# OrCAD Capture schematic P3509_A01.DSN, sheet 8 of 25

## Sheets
8 0017_DISPLAY PORT: size Custom
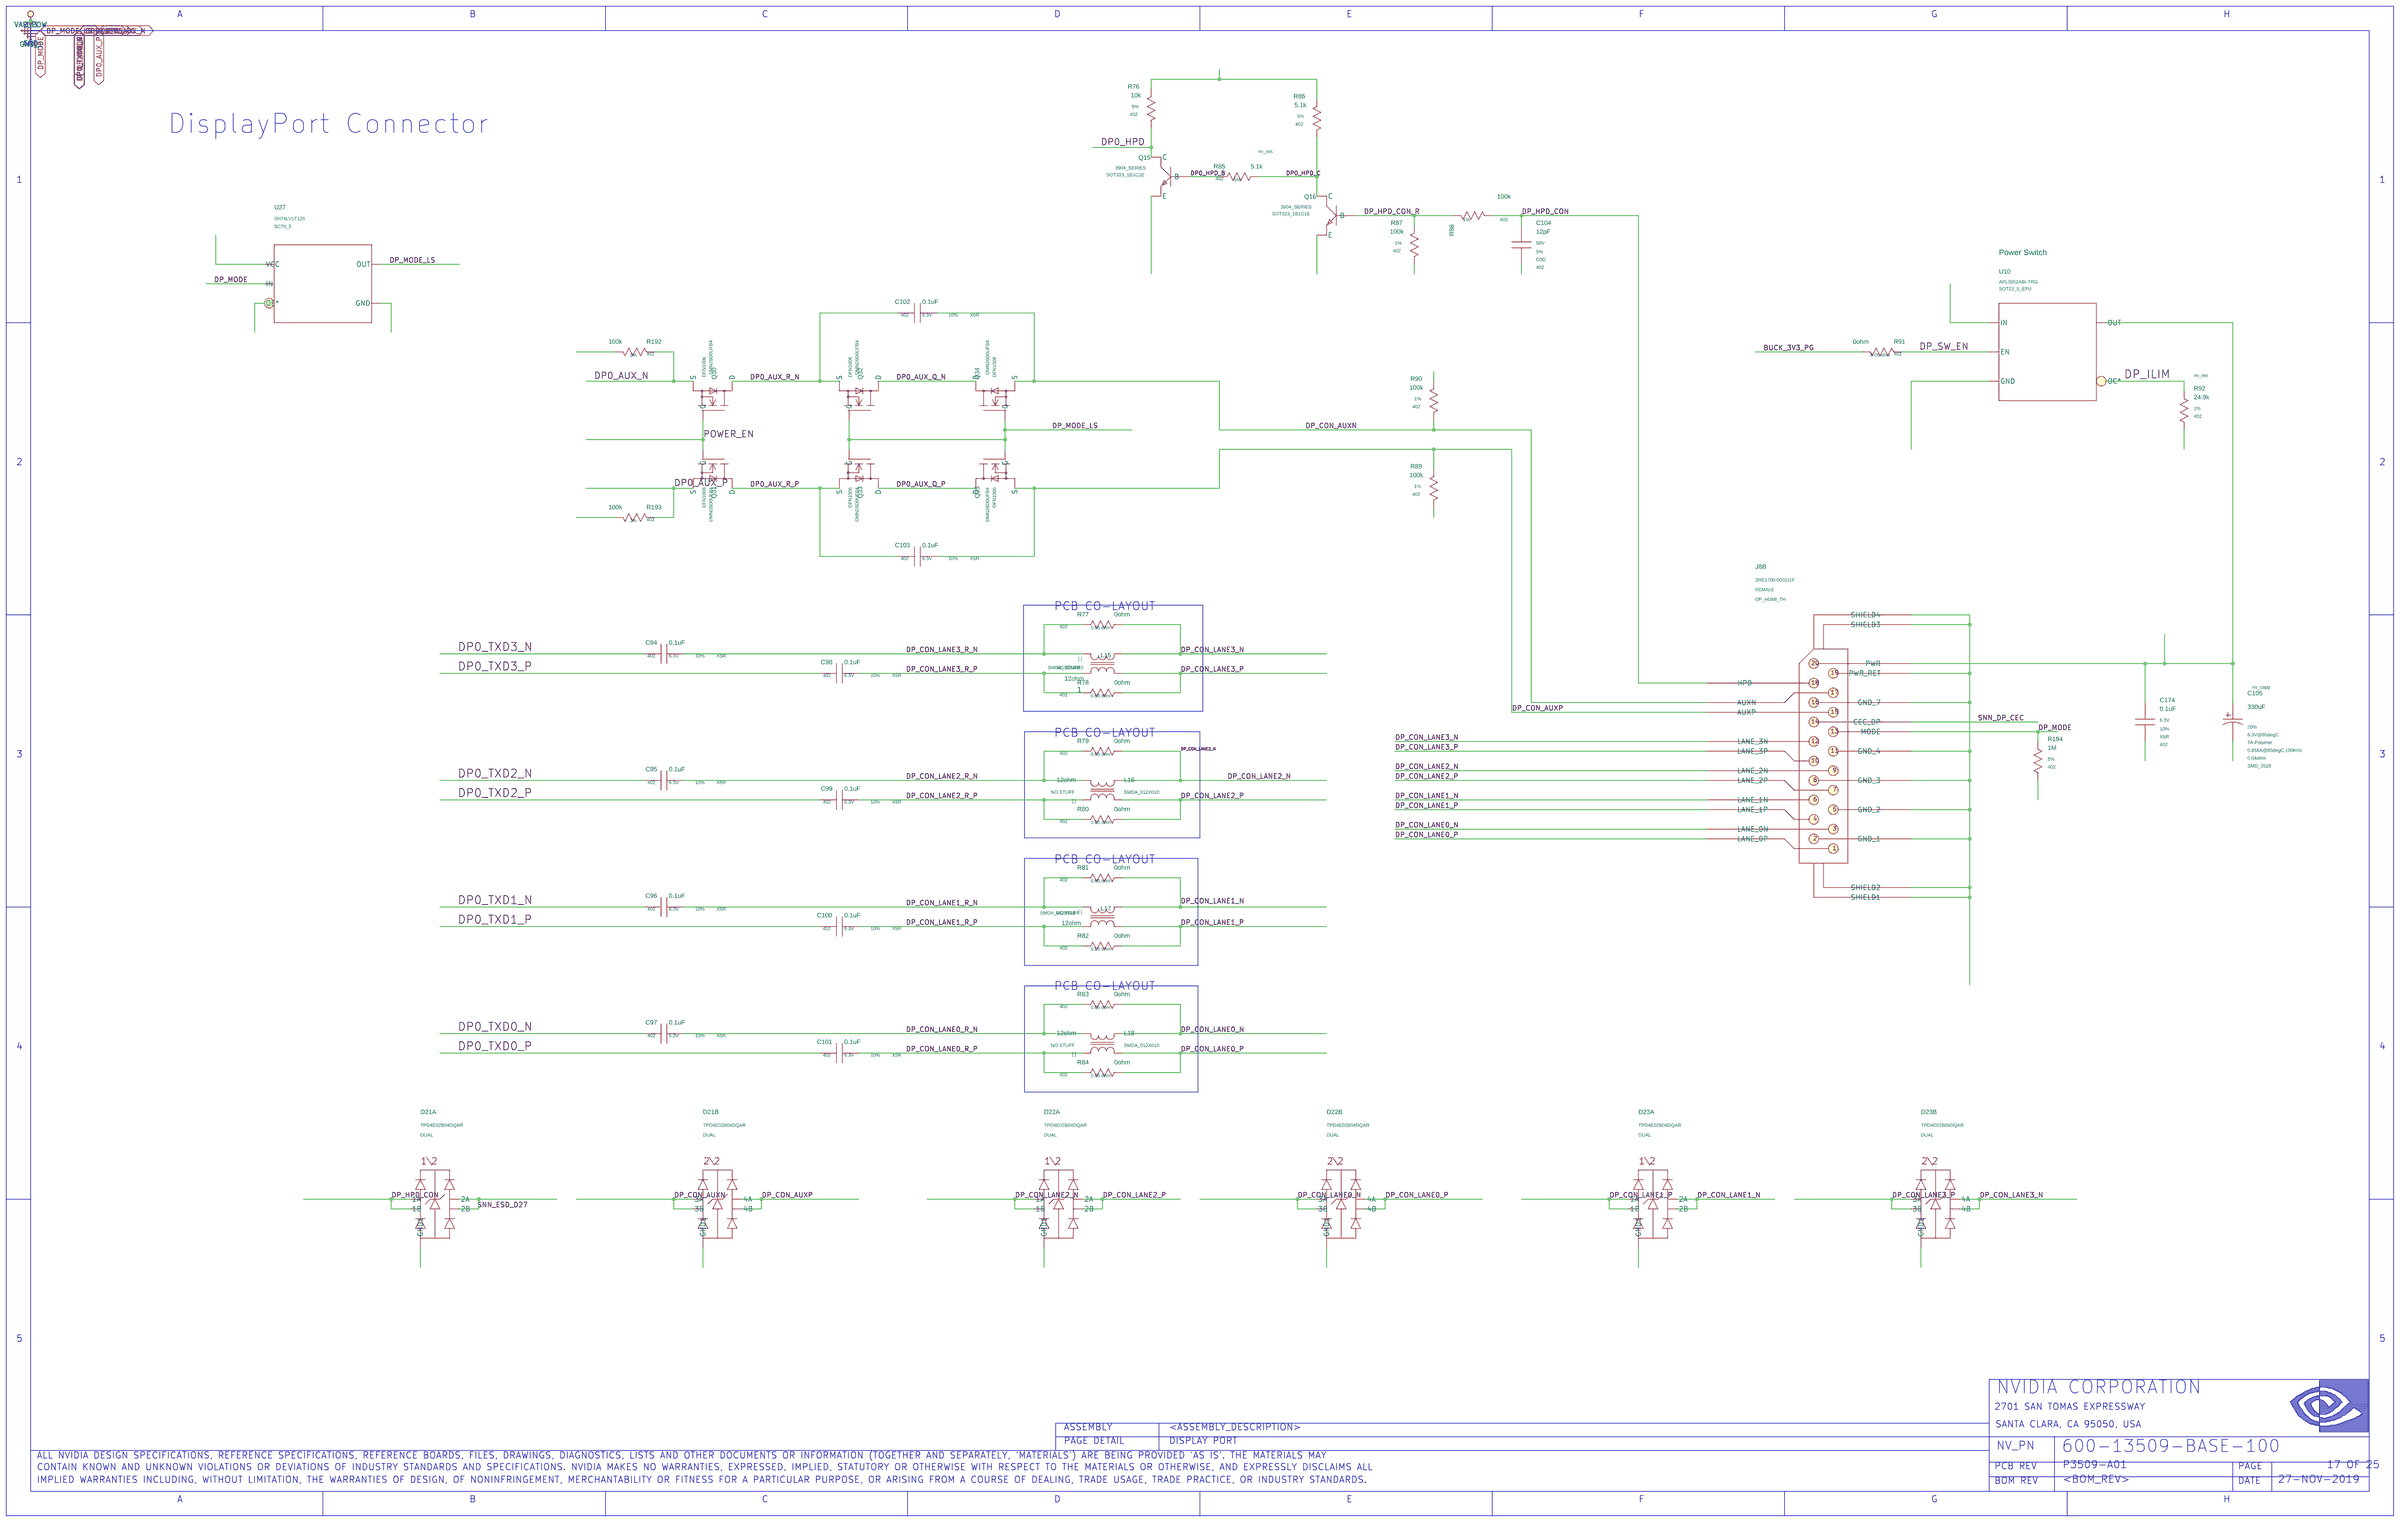
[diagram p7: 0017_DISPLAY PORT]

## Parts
sheet 0016_HDMI
J8  CON_HDMI_DISPLAYPORT  [CON_HDMI_019_DP_020_TH_RA_F_181X180_B]  (sections A,B)
sheet 0017_DISPLAY PORT
C94  0.1uF  [402]
C95  0.1uF  [402]
C96  0.1uF  [402]
C97  0.1uF  [402]
C98  0.1uF  [402]
C99  0.1uF  [402]
C100  0.1uF  [402]
C101  0.1uF  [402]
C102  0.1uF  [402]
C103  0.1uF  [402]
C104  12pF  [402]
C105  330uF  [CAP_SMD_3528]
C174  0.1uF  [402]
D21  D_ESD_DIFFPAIR  [TSLP10_P050_025X010]  (sections A,B)
D22  D_ESD_DIFFPAIR  [TSLP10_P050_025X010]  (sections A,B)
D23  D_ESD_DIFFPAIR  [TSLP10_P050_025X010]  (sections A,B)
L15  12ohm  [IND_NONRKO_SMD_012X010]
L16  12ohm  [IND_NONRKO_SMD_012X010]
L17  12ohm  [IND_NONRKO_SMD_012X010]
L18  12ohm  [IND_NONRKO_SMD_012X010]
Q15  Q_NPN  [SOT323_D]
Q16  Q_NPN  [SOT323_D]
Q30  Q_FET_N_ENH  [DFET_003_SMD_010X006_B]
Q31  Q_FET_N_ENH  [DFET_003_SMD_010X006_B]
Q32  Q_FET_N_ENH  [DFET_003_SMD_010X006_B]
Q33  Q_FET_N_ENH  [DFET_003_SMD_010X006_B]
Q34  Q_FET_N_ENH  [DFET_003_SMD_010X006_B]
Q35  Q_FET_N_ENH  [DFET_003_SMD_010X006_B]
R76  10k  [402]
R77  0ohm  [402]
R78  0ohm  [402]
R79  0ohm  [402]
R80  0ohm  [402]
R81  0ohm  [402]
R82  0ohm  [402]
R83  0ohm  [402]
R84  0ohm  [402]
R85  5.1k  [402]
R86  5.1k  [402]
R87  100k  [402]
R88  100k  [402]
R89  100k  [402]
R90  100k  [402]
R91  0ohm  [402]
R92  24.9k  [402]
R192  100k  [402]
R193  100k  [402]
R194  1M  [402]
U10  U_PWR_SW_UL  [SOT23_5]
U27  U_LEVSHFT_3STATE  [SC70_5]

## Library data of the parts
J8 = CON_HDMI_DISPLAYPORT: ANGLE: 90; ASSEMBLY: HDMI; CDS_LIB: electro_mechanic; CDS_PART_NAME: CON_HDMI_DISPLAYPORT_DP_HDMI_TH-2HE1700-000111F,FEMALE,1.4MM,90,YES,YES,YES,YES,YES,40 MV,500 MA,064-0374-000; CDS_PHYS_PART_NAME: CON_HDMI_DISPLAYPORT_DP_HDMI_TH-2HE1700-000111F,FEMALE,1.4MM,90,YES,YES,YES,YES,YES,40 MV,500 MA,064-0374-000-064-0374-000; CDS_SEC: 1; CaptureCellPackProp: CON_HDMI_DISPLAYPORTA; DEVICE_TYPENAME: CON_HDMI_DISPLAYPORT_DP_HDMI_TH-2HE1700-000111FFEMALE14MM90YESYESYESYESYES40MV500MA064-0374-000-064-0374-000; DRAWING: #NAME?; EMI_GROUND_TAB: YES; GENDER: FEMALE; LATCHING: YES; MAX_CURRENT: 500 mA; MAX_VOLTAGE: 40 mV; NV_NAME: 2HE1700-000111F; NV_PN: 064-0374-000; PACK_TYPE: DP_HDMI_TH; PATH: I25; PHYS_PAGE: 16; PITCH: 1.4mm; REFLOW: YES; ROT: 0; SEC: 1; SHIELDED: YES; SHROUDED: YES; VER: 1; XY: (-900,2900)
C94 = C: ASSEMBLY: DISPLAYPORT; CDS_LIB: discrete; CDS_PART_NAME: C_0402-0.1UF,X5R,10%,6.3V,039-0007-000; CDS_PHYS_PART_NAME: C_0402-0.1UF,X5R,10%,6.3V,039-0007-000-0.1UF,039-0007-000; CDS_SEC: 1; DEVICE_TYPENAME: C_0402-01UFX5R1063V039-0007-000-01UF039-0007-000; DRAWING: #NAME?; MAT: X5R; MAX_VOLTAGE: 6.3V; NO_XNET: 1; NV_PN: 039-0007-000; PATH: I55; PHYS_PAGE: 17; ROT: 0; SEC: 1; SIGNAL_MODEL: nv_cap; TOL: 10%; VER: 2; XY: (-8750,4300)
C95 = C: ASSEMBLY: DISPLAYPORT; CDS_LIB: discrete; CDS_PART_NAME: C_0402-0.1UF,X5R,10%,6.3V,039-0007-000; CDS_PHYS_PART_NAME: C_0402-0.1UF,X5R,10%,6.3V,039-0007-000-0.1UF,039-0007-000; CDS_SEC: 1; DEVICE_TYPENAME: C_0402-01UFX5R1063V039-0007-000-01UF039-0007-000; DRAWING: #NAME?; MAT: X5R; MAX_VOLTAGE: 6.3V; NO_XNET: 1; NV_PN: 039-0007-000; PATH: I58; PHYS_PAGE: 17; ROT: 0; SEC: 1; SIGNAL_MODEL: nv_cap; TOL: 10%; VER: 2; XY: (-8750,3650)
C96 = C: ASSEMBLY: DISPLAYPORT; CDS_LIB: discrete; CDS_PART_NAME: C_0402-0.1UF,X5R,10%,6.3V,039-0007-000; CDS_PHYS_PART_NAME: C_0402-0.1UF,X5R,10%,6.3V,039-0007-000-0.1UF,039-0007-000; CDS_SEC: 1; DEVICE_TYPENAME: C_0402-01UFX5R1063V039-0007-000-01UF039-0007-000; DRAWING: #NAME?; MAT: X5R; MAX_VOLTAGE: 6.3V; NO_XNET: 1; NV_PN: 039-0007-000; PATH: I62; PHYS_PAGE: 17; ROT: 0; SEC: 1; SIGNAL_MODEL: nv_cap; TOL: 10%; VER: 2; XY: (-8750,3000)
C97 = C: ASSEMBLY: DISPLAYPORT; CDS_LIB: discrete; CDS_PART_NAME: C_0402-0.1UF,X5R,10%,6.3V,039-0007-000; CDS_PHYS_PART_NAME: C_0402-0.1UF,X5R,10%,6.3V,039-0007-000-0.1UF,039-0007-000; CDS_SEC: 1; DEVICE_TYPENAME: C_0402-01UFX5R1063V039-0007-000-01UF039-0007-000; DRAWING: #NAME?; MAT: X5R; MAX_VOLTAGE: 6.3V; NO_XNET: 1; NV_PN: 039-0007-000; PATH: I63; PHYS_PAGE: 17; ROT: 0; SEC: 1; SIGNAL_MODEL: nv_cap; TOL: 10%; VER: 2; XY: (-8750,2350)
C98 = C: ASSEMBLY: DISPLAYPORT; CDS_LIB: discrete; CDS_PART_NAME: C_0402-0.1UF,X5R,10%,6.3V,039-0007-000; CDS_PHYS_PART_NAME: C_0402-0.1UF,X5R,10%,6.3V,039-0007-000-0.1UF,039-0007-000; CDS_SEC: 1; DEVICE_TYPENAME: C_0402-01UFX5R1063V039-0007-000-01UF039-0007-000; DRAWING: #NAME?; MAT: X5R; MAX_VOLTAGE: 6.3V; NO_XNET: 1; NV_PN: 039-0007-000; PATH: I54; PHYS_PAGE: 17; ROT: 0; SEC: 1; SIGNAL_MODEL: nv_cap; TOL: 10%; VER: 2; XY: (-7850,4200)
C99 = C: ASSEMBLY: DISPLAYPORT; CDS_LIB: discrete; CDS_PART_NAME: C_0402-0.1UF,X5R,10%,6.3V,039-0007-000; CDS_PHYS_PART_NAME: C_0402-0.1UF,X5R,10%,6.3V,039-0007-000-0.1UF,039-0007-000; CDS_SEC: 1; DEVICE_TYPENAME: C_0402-01UFX5R1063V039-0007-000-01UF039-0007-000; DRAWING: #NAME?; MAT: X5R; MAX_VOLTAGE: 6.3V; NO_XNET: 1; NV_PN: 039-0007-000; PATH: I59; PHYS_PAGE: 17; ROT: 0; SEC: 1; SIGNAL_MODEL: nv_cap; TOL: 10%; VER: 2; XY: (-7850,3550)
C100 = C: ASSEMBLY: DISPLAYPORT; CDS_LIB: discrete; CDS_PART_NAME: C_0402-0.1UF,X5R,10%,6.3V,039-0007-000; CDS_PHYS_PART_NAME: C_0402-0.1UF,X5R,10%,6.3V,039-0007-000-0.1UF,039-0007-000; CDS_SEC: 1; DEVICE_TYPENAME: C_0402-01UFX5R1063V039-0007-000-01UF039-0007-000; DRAWING: #NAME?; MAT: X5R; MAX_VOLTAGE: 6.3V; NO_XNET: 1; NV_PN: 039-0007-000; PATH: I60; PHYS_PAGE: 17; ROT: 0; SEC: 1; SIGNAL_MODEL: nv_cap; TOL: 10%; VER: 2; XY: (-7850,2900)
C101 = C: ASSEMBLY: DISPLAYPORT; CDS_LIB: discrete; CDS_PART_NAME: C_0402-0.1UF,X5R,10%,6.3V,039-0007-000; CDS_PHYS_PART_NAME: C_0402-0.1UF,X5R,10%,6.3V,039-0007-000-0.1UF,039-0007-000; CDS_SEC: 1; DEVICE_TYPENAME: C_0402-01UFX5R1063V039-0007-000-01UF039-0007-000; DRAWING: #NAME?; MAT: X5R; MAX_VOLTAGE: 6.3V; NO_XNET: 1; NV_PN: 039-0007-000; PATH: I61; PHYS_PAGE: 17; ROT: 0; SEC: 1; SIGNAL_MODEL: nv_cap; TOL: 10%; VER: 2; XY: (-7850,2250)
C102 = C: ASSEMBLY: DISPLAYPORT; CDS_LIB: discrete; CDS_PART_NAME: C_0402-0.1UF,X5R,10%,6.3V,039-0007-000; CDS_PHYS_PART_NAME: C_0402-0.1UF,X5R,10%,6.3V,039-0007-000-0.1UF,039-0007-000; CDS_SEC: 1; DEVICE_TYPENAME: C_0402-01UFX5R1063V039-0007-000-01UF039-0007-000; DRAWING: #NAME?; MAT: X5R; MAX_VOLTAGE: 6.3V; NV_PN: 039-0007-000; PATH: I74; PHYS_PAGE: 17; ROT: 0; SEC: 1; SIGNAL_MODEL: nv_cap; TOL: 10%; VER: 2; XY: (-7450,6050)
C103 = C: ASSEMBLY: DISPLAYPORT; CDS_LIB: discrete; CDS_PART_NAME: C_0402-0.1UF,X5R,10%,6.3V,039-0007-000; CDS_PHYS_PART_NAME: C_0402-0.1UF,X5R,10%,6.3V,039-0007-000-0.1UF,039-0007-000; CDS_SEC: 1; DEVICE_TYPENAME: C_0402-01UFX5R1063V039-0007-000-01UF039-0007-000; DRAWING: #NAME?; MAT: X5R; MAX_VOLTAGE: 6.3V; NV_PN: 039-0007-000; PATH: I75; PHYS_PAGE: 17; ROT: 0; SEC: 1; SIGNAL_MODEL: nv_cap; TOL: 10%; VER: 2; XY: (-7450,4800)
C104 = C#1_v2: ASSEMBLY: DISPLAYPORT; CDS_LIB: discrete; CDS_PART_NAME: C_0402-12PF,C0G,5%,50V,035-0014-000; CDS_PHYS_PART_NAME: C_0402-12PF,C0G,5%,50V,035-0014-000-035-0014-000,12PF; CDS_SEC: 1; CHIPS_PART_NAME: C; DEVICE_TYPENAME: C_0402-12PFC0G550V035-0014-000-035-0014-00012PF; DRAWING: #NAME?; ESL: N/A; ESR: N/A; MAT: C0G; MAX_VOLTAGE: 50V; NV_PN: 035-0014-000; PATH: I21; PHYS_PAGE: 17; ROT: 0; SEC: 1; SIGNAL_MODEL: nv_cap; TOL: 5%; VER: 1; XY: (-4350,6400)
C105 = C_POL: ASSEMBLY: DISPLAYPORT; CDS_LIB: discrete; CDS_PART_NAME: C_POL_SMD_3528-330UF,TA-POLYMER,20%,6.3V@85DEGC,0.04OHM,9.999UH,0.855A@85DEGC,100KHZ,032-0696-000; CDS_PHYS_PART_NAME: C_POL_SMD_3528-330UF,TA-POLYMER,20%,6.3V@85DEGC,0.04OHM,9.999UH,0.855A@85DEGC,100KHZ,032-0696-000-032-0696-000,330UF; CDS_SEC: 1; DEVICE_TYPENAME: C_POL_SMD_3528-330UFTA-POLYMER2063V85DEGC004OHM9999UH0855A85DEGC100KHZ032-0696-000-032-0696-000330UF; DRAWING: #NAME?; ESL: 9.999uH; ESR: 0.04ohm; MAT: TA-Polymer; MAX_VOLTAGE: 6.3V@85degC; NV_PN: 032-0696-000; PACK_TYPE: SMD_3528; PATH: I9; PHYS_PAGE: 17; RIPPLE_CURRENT: 0.855A@85degC,100KHz; ROT: 0; SEC: 1; SIGNAL_MODEL: nv_capp; TOL: 20%; VER: 1; XY: (-700,3950)
C174 = C#1_v2: ASSEMBLY: DISPLAYPORT; CDS_LIB: discrete; CDS_PART_NAME: C_0402-0.1UF,X5R,10%,6.3V,039-0007-000; CDS_PHYS_PART_NAME: C_0402-0.1UF,X5R,10%,6.3V,039-0007-000-0.1UF,039-0007-000; CDS_SEC: 1; CHIPS_PART_NAME: C; DEVICE_TYPENAME: C_0402-01UFX5R1063V039-0007-000-01UF039-0007-000; DRAWING: #NAME?; MAT: X5R; MAX_VOLTAGE: 6.3V; NV_PN: 039-0007-000; PATH: I106; PHYS_PAGE: 17; ROT: 0; SEC: 1; TOL: 10%; VER: 1; XY: (-1150,3950)
D21 = D_ESD_DIFFPAIR: ASSEMBLY: DISPLAYPORT; BREAKDOWN_VOLTAGE_MIN_TYP: 6.7V; CAPACITANCE_MAX_TYP: 0.37pF; CDS_LIB: discrete; CDS_PART_NAME: D_ESD_DIFFPAIR_DUAL-TPD4E02B04DQAR,2 DIFFPAIR,BI-DIRECTIONAL,6V,0.01UA,6.7V,8V@40A,0.37PF,090-0296-000; CDS_PHYS_PART_NAME: D_ESD_DIFFPAIR_DUAL-TPD4E02B04DQAR,2 DIFFPAIR,BI-DIRECTIONAL,6V,0.01UA,6.7V,8V@40A,0.37PF,090-0296-000-090-0296-000; CDS_SEC: 1; CLAMPING_VOLTAGE: 8V@40A; CONFIGURATION: 2 Diffpair; CaptureCellPackProp: D_ESD_DIFFPAIRA; DEVICE_TYPENAME: D_ESD_DIFFPAIR_DUAL-TPD4E02B04DQAR2DIFFPAIRBI-DIRECTIONAL6V001UA67V8V40A037PF090-0296-000-090-0296-000; DRAWING: #NAME?; MAX_REVERSE_LEAKAGE_CURRENT: 0.01uA; MAX_REVERSE_VOLTAGE: 6V; NV_NAME: TPD4E02B04DQAR; NV_PN: 090-0296-000; PACK_TYPE: DUAL; PATH: I67; PHYS_PAGE: 17; POLARITY: Bi-Directional; ROT: 0; SEC: 1; VER: 1; XY: (-9950,1500)
D22 = D_ESD_DIFFPAIR: ASSEMBLY: DISPLAYPORT; BREAKDOWN_VOLTAGE_MIN_TYP: 6.7V; CAPACITANCE_MAX_TYP: 0.37pF; CDS_LIB: discrete; CDS_PART_NAME: D_ESD_DIFFPAIR_DUAL-TPD4E02B04DQAR,2 DIFFPAIR,BI-DIRECTIONAL,6V,0.01UA,6.7V,8V@40A,0.37PF,090-0296-000; CDS_PHYS_PART_NAME: D_ESD_DIFFPAIR_DUAL-TPD4E02B04DQAR,2 DIFFPAIR,BI-DIRECTIONAL,6V,0.01UA,6.7V,8V@40A,0.37PF,090-0296-000-090-0296-000; CDS_SEC: 1; CLAMPING_VOLTAGE: 8V@40A; CONFIGURATION: 2 Diffpair; CaptureCellPackProp: D_ESD_DIFFPAIRA; DEVICE_TYPENAME: D_ESD_DIFFPAIR_DUAL-TPD4E02B04DQAR2DIFFPAIRBI-DIRECTIONAL6V001UA67V8V40A037PF090-0296-000-090-0296-000; DRAWING: #NAME?; MAX_REVERSE_LEAKAGE_CURRENT: 0.01uA; MAX_REVERSE_VOLTAGE: 6V; NV_NAME: TPD4E02B04DQAR; NV_PN: 090-0296-000; PACK_TYPE: DUAL; PATH: I52; PHYS_PAGE: 17; POLARITY: Bi-Directional; ROT: 0; SEC: 1; VER: 1; XY: (-6750,1500)
D23 = D_ESD_DIFFPAIR: ASSEMBLY: DISPLAYPORT; BREAKDOWN_VOLTAGE_MIN_TYP: 6.7V; CAPACITANCE_MAX_TYP: 0.37pF; CDS_LIB: discrete; CDS_PART_NAME: D_ESD_DIFFPAIR_DUAL-TPD4E02B04DQAR,2 DIFFPAIR,BI-DIRECTIONAL,6V,0.01UA,6.7V,8V@40A,0.37PF,090-0296-000; CDS_PHYS_PART_NAME: D_ESD_DIFFPAIR_DUAL-TPD4E02B04DQAR,2 DIFFPAIR,BI-DIRECTIONAL,6V,0.01UA,6.7V,8V@40A,0.37PF,090-0296-000-090-0296-000; CDS_SEC: 1; CLAMPING_VOLTAGE: 8V@40A; CONFIGURATION: 2 Diffpair; CaptureCellPackProp: D_ESD_DIFFPAIRA; DEVICE_TYPENAME: D_ESD_DIFFPAIR_DUAL-TPD4E02B04DQAR2DIFFPAIRBI-DIRECTIONAL6V001UA67V8V40A037PF090-0296-000-090-0296-000; DRAWING: #NAME?; MAX_REVERSE_LEAKAGE_CURRENT: 0.01uA; MAX_REVERSE_VOLTAGE: 6V; NV_NAME: TPD4E02B04DQAR; NV_PN: 090-0296-000; PACK_TYPE: DUAL; PATH: I14; PHYS_PAGE: 17; POLARITY: Bi-Directional; ROT: 0; SEC: 1; VER: 1; XY: (-3700,1500)
L15 = L_CMF_4P#1: ASSEMBLY: DISPLAYPORT; CDS_LIB: discrete; CDS_PART_NAME: L_CMF_4P_SMDA_012X010-12OHM,[ ],25%,0.1A,1.5OHM,MCZ1210DH120L2TA0G,102-0066-000; CDS_PHYS_PART_NAME: L_CMF_4P_SMDA_012X010-12OHM,[ ],25%,0.1A,1.5OHM,MCZ1210DH120L2TA0G,102-0066-000-102-0066-000,12OHM; CDS_SEC: 1; CHIPS_PART_NAME: L_CMF_4P; DC_RESISTANCE: 1.5ohm; DEVICE_TYPENAME: L_CMF_4P_SMDA_012X010-12OHM2501A15OHMMCZ1210DH120L2TA0G102-0066-000-102-0066-00012OHM; DRAWING: #NAME?; MAT: [ ]; MAX_CURRENT: 0.1A; NO_XNET_CONNECTION: 1; NV_NAME: MCZ1210DH120L2TA0G; NV_PN: 102-0066-000; PACK_TYPE: SMDA_012X010; PATH: I36; PHYS_PAGE: 17; PLACEMENT_NOTE: CoLayout with R563, R565; ROT: 4; SEC: 1; SIGNAL_MODEL: nv_ind_cmf_4p; SKU: NO STUFF; TOL: 25%; VER: 1; XY: (-6500,4250)
L16 = L_CMF_4P#1: ASSEMBLY: DISPLAYPORT; CDS_LIB: discrete; CDS_PART_NAME: L_CMF_4P_SMDA_012X010-12OHM,[ ],25%,0.1A,1.5OHM,MCZ1210DH120L2TA0G,102-0066-000; CDS_PHYS_PART_NAME: L_CMF_4P_SMDA_012X010-12OHM,[ ],25%,0.1A,1.5OHM,MCZ1210DH120L2TA0G,102-0066-000-102-0066-000,12OHM; CDS_SEC: 1; CHIPS_PART_NAME: L_CMF_4P; DC_RESISTANCE: 1.5ohm; DEVICE_TYPENAME: L_CMF_4P_SMDA_012X010-12OHM2501A15OHMMCZ1210DH120L2TA0G102-0066-000-102-0066-00012OHM; DRAWING: #NAME?; MAT: [ ]; MAX_CURRENT: 0.1A; NV_NAME: MCZ1210DH120L2TA0G; NV_PN: 102-0066-000; PACK_TYPE: SMDA_012X010; PATH: I44; PHYS_PAGE: 17; PLACEMENT_NOTE: CoLayout with R568, R571; ROT: 2; SEC: 1; SIGNAL_MODEL: nv_ind_cmf_4p; SKU: NO STUFF; TOL: 25%; VER: 1; XY: (-6500,3600)
L17 = L_CMF_4P#1: ASSEMBLY: DISPLAYPORT; CDS_LIB: discrete; CDS_PART_NAME: L_CMF_4P_SMDA_012X010-12OHM,[ ],25%,0.1A,1.5OHM,MCZ1210DH120L2TA0G,102-0066-000; CDS_PHYS_PART_NAME: L_CMF_4P_SMDA_012X010-12OHM,[ ],25%,0.1A,1.5OHM,MCZ1210DH120L2TA0G,102-0066-000-102-0066-000,12OHM; CDS_SEC: 1; CHIPS_PART_NAME: L_CMF_4P; DC_RESISTANCE: 1.5ohm; DEVICE_TYPENAME: L_CMF_4P_SMDA_012X010-12OHM2501A15OHMMCZ1210DH120L2TA0G102-0066-000-102-0066-00012OHM; DRAWING: #NAME?; MAT: [ ]; MAX_CURRENT: 0.1A; NV_NAME: MCZ1210DH120L2TA0G; NV_PN: 102-0066-000; PACK_TYPE: SMDA_012X010; PATH: I47; PHYS_PAGE: 17; PLACEMENT_NOTE: CoLayout with R577, R579; ROT: 4; SEC: 1; SIGNAL_MODEL: nv_ind_cmf_4p; SKU: NO STUFF; TOL: 25%; VER: 1; XY: (-6500,2950)
L18 = L_CMF_4P#1: ASSEMBLY: DISPLAYPORT; CDS_LIB: discrete; CDS_PART_NAME: L_CMF_4P_SMDA_012X010-12OHM,[ ],25%,0.1A,1.5OHM,MCZ1210DH120L2TA0G,102-0066-000; CDS_PHYS_PART_NAME: L_CMF_4P_SMDA_012X010-12OHM,[ ],25%,0.1A,1.5OHM,MCZ1210DH120L2TA0G,102-0066-000-102-0066-000,12OHM; CDS_SEC: 1; CHIPS_PART_NAME: L_CMF_4P; DC_RESISTANCE: 1.5ohm; DEVICE_TYPENAME: L_CMF_4P_SMDA_012X010-12OHM2501A15OHMMCZ1210DH120L2TA0G102-0066-000-102-0066-00012OHM; DRAWING: #NAME?; MAT: [ ]; MAX_CURRENT: 0.1A; NV_NAME: MCZ1210DH120L2TA0G; NV_PN: 102-0066-000; PACK_TYPE: SMDA_012X010; PATH: I50; PHYS_PAGE: 17; PLACEMENT_NOTE: CoLayout with R583, R584; ROT: 2; SEC: 1; SIGNAL_MODEL: nv_ind_cmf_4p; SKU: NO STUFF; TOL: 25%; VER: 1; XY: (-6500,2300)
Q15 = Q_NPN: ASSEMBLY: DISPLAYPORT; CDS_LIB: discrete; CDS_PART_NAME: Q_NPN_SOT323_1B1C1E-3904_SERIES,40V,0.3V,0.2A,0.2A,6V,0.15W,300-1128-000; CDS_PHYS_PART_NAME: Q_NPN_SOT323_1B1C1E-3904_SERIES,40V,0.3V,0.2A,0.2A,6V,0.15W,300-1128-000-300-1128-000; CDS_SEC: 1; CONTINUOUS_CURRENT: 0.2A; DEVICE_TYPENAME: Q_NPN_SOT323_1B1C1E-3904_SERIES40V03V02A02A6V015W300-1128-000-300-1128-000; DRAWING: #NAME?; MAX_CURRENT: 0.2A; MAX_VOLTAGE: 40V; MAX_WATTAGE: 0.15W; NV_NAME: 3904_SERIES; NV_PN: 300-1128-000; PACK_TYPE: SOT323_1B1C1E; PATH: I30; PHYS_PAGE: 17; ROT: 2; SEC: 1; VER: 1; V_BE_GS: 6V; V_CE_SAT: 0.3V; XY: (-6150,6750)
Q16 = Q_NPN: ASSEMBLY: DISPLAYPORT; CDS_LIB: discrete; CDS_PART_NAME: Q_NPN_SOT323_1B1C1E-3904_SERIES,40V,0.3V,0.2A,0.2A,6V,0.15W,300-1128-000; CDS_PHYS_PART_NAME: Q_NPN_SOT323_1B1C1E-3904_SERIES,40V,0.3V,0.2A,0.2A,6V,0.15W,300-1128-000-300-1128-000; CDS_SEC: 1; CONTINUOUS_CURRENT: 0.2A; DEVICE_TYPENAME: Q_NPN_SOT323_1B1C1E-3904_SERIES40V03V02A02A6V015W300-1128-000-300-1128-000; DRAWING: #NAME?; MAX_CURRENT: 0.2A; MAX_VOLTAGE: 40V; MAX_WATTAGE: 0.15W; NV_NAME: 3904_SERIES; NV_PN: 300-1128-000; PACK_TYPE: SOT323_1B1C1E; PATH: I32; PHYS_PAGE: 17; ROT: 2; SEC: 1; VER: 1; V_BE_GS: 6V; V_CE_SAT: 0.3V; XY: (-5300,6550)
Q30 = Q_FET_N_ENH#1: ASSEMBLY: DISPLAYPORT; CDS_LIB: discrete; CDS_PART_NAME: Q_FET_N_ENH_DFN1006-DMN26D0UFB4,20V,999MOHM@10V / 3000MOHM@4.5V / 4000MOHM@2.5V,0.14A,0.805A,10V,0.35W,999NC@10V / 0NC@4.5V / A; CDS_PHYS_PART_NAME: Q_FET_N_ENH_DFN1006-DMN26D0UFB4,20V,999MOHM@10V / 3000MOHM@4.5V / 4000MOHM@2.5V,0.14A,0.805A,10V,0.35W,999NC@10V / 0NC@4.5V / B; CDS_SEC: 1; CONTINUOUS_CURRENT: 0.14A; CaptureCellPackProp: Q_FET_N_ENH##1; DEVICE_TYPENAME: Q_FET_N_ENH_DFN1006-DMN26D0UFB420V999MOHM10V3000MOHM45V4000MOHM25V014A0805A10V035W999NC10V0NC45VB; DRAWING: #NAME?; MAX_CURRENT: 0.805A; MAX_VOLTAGE: 20V; MAX_WATTAGE: 0.35W; NV_NAME: DMN26D0UFB4; NV_PN: 300-0868-000; PACK_TYPE: DFN1006; PATH: I103; PHYS_PAGE: 17; Q_G: 999nC@10V / 0nC@4.5V / 999nC@2.5V; ROT: 7; R_DS_ON: 999mohm@10V / 3000mohm@4.5V / 4000mohm@2.5V; SEC: 1; VER: 2; V_BE_GS: 10V; XY: (-8500,5600)
Q31 = Q_FET_N_ENH#1: ASSEMBLY: DISPLAYPORT; CDS_LIB: discrete; CDS_PART_NAME: Q_FET_N_ENH_DFN1006-DMN26D0UFB4,20V,999MOHM@10V / 3000MOHM@4.5V / 4000MOHM@2.5V,0.14A,0.805A,10V,0.35W,999NC@10V / 0NC@4.5V / A; CDS_PHYS_PART_NAME: Q_FET_N_ENH_DFN1006-DMN26D0UFB4,20V,999MOHM@10V / 3000MOHM@4.5V / 4000MOHM@2.5V,0.14A,0.805A,10V,0.35W,999NC@10V / 0NC@4.5V / B; CDS_SEC: 1; CONTINUOUS_CURRENT: 0.14A; CaptureCellPackProp: Q_FET_N_ENH##1; DEVICE_TYPENAME: Q_FET_N_ENH_DFN1006-DMN26D0UFB420V999MOHM10V3000MOHM45V4000MOHM25V014A0805A10V035W999NC10V0NC45VB; DRAWING: #NAME?; MAX_CURRENT: 0.805A; MAX_VOLTAGE: 20V; MAX_WATTAGE: 0.35W; NV_NAME: DMN26D0UFB4; NV_PN: 300-0868-000; PACK_TYPE: DFN1006; PATH: I104; PHYS_PAGE: 17; Q_G: 999nC@10V / 0nC@4.5V / 999nC@2.5V; ROT: 5; R_DS_ON: 999mohm@10V / 3000mohm@4.5V / 4000mohm@2.5V; SEC: 1; VER: 2; V_BE_GS: 10V; XY: (-8500,5250)
Q32 = Q_FET_N_ENH#1: ASSEMBLY: DISPLAYPORT; CDS_LIB: discrete; CDS_PART_NAME: Q_FET_N_ENH_DFN1006-DMN26D0UFB4,20V,999MOHM@10V / 3000MOHM@4.5V / 4000MOHM@2.5V,0.14A,0.805A,10V,0.35W,999NC@10V / 0NC@4.5V / A; CDS_PHYS_PART_NAME: Q_FET_N_ENH_DFN1006-DMN26D0UFB4,20V,999MOHM@10V / 3000MOHM@4.5V / 4000MOHM@2.5V,0.14A,0.805A,10V,0.35W,999NC@10V / 0NC@4.5V / B; CDS_SEC: 1; CONTINUOUS_CURRENT: 0.14A; CaptureCellPackProp: Q_FET_N_ENH##1; DEVICE_TYPENAME: Q_FET_N_ENH_DFN1006-DMN26D0UFB420V999MOHM10V3000MOHM45V4000MOHM25V014A0805A10V035W999NC10V0NC45VB; DRAWING: #NAME?; MAX_CURRENT: 0.805A; MAX_VOLTAGE: 20V; MAX_WATTAGE: 0.35W; NV_NAME: DMN26D0UFB4; NV_PN: 300-0868-000; PACK_TYPE: DFN1006; PATH: I99; PHYS_PAGE: 17; Q_G: 999nC@10V / 0nC@4.5V / 999nC@2.5V; ROT: 7; R_DS_ON: 999mohm@10V / 3000mohm@4.5V / 4000mohm@2.5V; SEC: 1; VER: 2; V_BE_GS: 10V; XY: (-7750,5600)
Q33 = Q_FET_N_ENH#1: ASSEMBLY: DISPLAYPORT; CDS_LIB: discrete; CDS_PART_NAME: Q_FET_N_ENH_DFN1006-DMN26D0UFB4,20V,999MOHM@10V / 3000MOHM@4.5V / 4000MOHM@2.5V,0.14A,0.805A,10V,0.35W,999NC@10V / 0NC@4.5V / A; CDS_PHYS_PART_NAME: Q_FET_N_ENH_DFN1006-DMN26D0UFB4,20V,999MOHM@10V / 3000MOHM@4.5V / 4000MOHM@2.5V,0.14A,0.805A,10V,0.35W,999NC@10V / 0NC@4.5V / B; CDS_SEC: 1; CONTINUOUS_CURRENT: 0.14A; CaptureCellPackProp: Q_FET_N_ENH##1; DEVICE_TYPENAME: Q_FET_N_ENH_DFN1006-DMN26D0UFB420V999MOHM10V3000MOHM45V4000MOHM25V014A0805A10V035W999NC10V0NC45VB; DRAWING: #NAME?; MAX_CURRENT: 0.805A; MAX_VOLTAGE: 20V; MAX_WATTAGE: 0.35W; NV_NAME: DMN26D0UFB4; NV_PN: 300-0868-000; PACK_TYPE: DFN1006; PATH: I101; PHYS_PAGE: 17; Q_G: 999nC@10V / 0nC@4.5V / 999nC@2.5V; ROT: 5; R_DS_ON: 999mohm@10V / 3000mohm@4.5V / 4000mohm@2.5V; SEC: 1; VER: 2; V_BE_GS: 10V; XY: (-7750,5250)
Q34 = Q_FET_N_ENH#1: ASSEMBLY: DISPLAYPORT; CDS_LIB: discrete; CDS_PART_NAME: Q_FET_N_ENH_DFN1006-DMN26D0UFB4,20V,999MOHM@10V / 3000MOHM@4.5V / 4000MOHM@2.5V,0.14A,0.805A,10V,0.35W,999NC@10V / 0NC@4.5V / A; CDS_PHYS_PART_NAME: Q_FET_N_ENH_DFN1006-DMN26D0UFB4,20V,999MOHM@10V / 3000MOHM@4.5V / 4000MOHM@2.5V,0.14A,0.805A,10V,0.35W,999NC@10V / 0NC@4.5V / B; CDS_SEC: 1; CONTINUOUS_CURRENT: 0.14A; CaptureCellPackProp: Q_FET_N_ENH##1; DEVICE_TYPENAME: Q_FET_N_ENH_DFN1006-DMN26D0UFB420V999MOHM10V3000MOHM45V4000MOHM25V014A0805A10V035W999NC10V0NC45VB; DRAWING: #NAME?; MAX_CURRENT: 0.805A; MAX_VOLTAGE: 20V; MAX_WATTAGE: 0.35W; NV_NAME: DMN26D0UFB4; NV_PN: 300-0868-000; PACK_TYPE: DFN1006; PATH: I100; PHYS_PAGE: 17; Q_G: 999nC@10V / 0nC@4.5V / 999nC@2.5V; ROT: 1; R_DS_ON: 999mohm@10V / 3000mohm@4.5V / 4000mohm@2.5V; SEC: 1; VER: 2; V_BE_GS: 10V; XY: (-7050,5600)
Q35 = Q_FET_N_ENH#1: ASSEMBLY: DISPLAYPORT; CDS_LIB: discrete; CDS_PART_NAME: Q_FET_N_ENH_DFN1006-DMN26D0UFB4,20V,999MOHM@10V / 3000MOHM@4.5V / 4000MOHM@2.5V,0.14A,0.805A,10V,0.35W,999NC@10V / 0NC@4.5V / A; CDS_PHYS_PART_NAME: Q_FET_N_ENH_DFN1006-DMN26D0UFB4,20V,999MOHM@10V / 3000MOHM@4.5V / 4000MOHM@2.5V,0.14A,0.805A,10V,0.35W,999NC@10V / 0NC@4.5V / B; CDS_SEC: 1; CONTINUOUS_CURRENT: 0.14A; CaptureCellPackProp: Q_FET_N_ENH##1; DEVICE_TYPENAME: Q_FET_N_ENH_DFN1006-DMN26D0UFB420V999MOHM10V3000MOHM45V4000MOHM25V014A0805A10V035W999NC10V0NC45VB; DRAWING: #NAME?; MAX_CURRENT: 0.805A; MAX_VOLTAGE: 20V; MAX_WATTAGE: 0.35W; NV_NAME: DMN26D0UFB4; NV_PN: 300-0868-000; PACK_TYPE: DFN1006; PATH: I102; PHYS_PAGE: 17; Q_G: 999nC@10V / 0nC@4.5V / 999nC@2.5V; ROT: 3; R_DS_ON: 999mohm@10V / 3000mohm@4.5V / 4000mohm@2.5V; SEC: 1; VER: 2; V_BE_GS: 10V; XY: (-7050,5250)
R76 = R: ASSEMBLY: DISPLAYPORT; CDS_LIB: discrete; CDS_PART_NAME: R_0402-10K,5 %,62.5MW,195-0486-000; CDS_PHYS_PART_NAME: R_0402-10K,5 %,62.5MW,195-0486-000-10K,195-0486-000; CDS_SEC: 1; DEVICE_TYPENAME: R_0402-10K5625MW195-0486-000-10K195-0486-000; DRAWING: #NAME?; MAX_WATTAGE: 62.5mW; NV_PN: 195-0486-000; PATH: I29; PHYS_PAGE: 17; ROT: 2; SEC: 1; SIGNAL_MODEL: nv_res; TOL: 5%; VER: 2; XY: (-6250,7100)
R77 = R#1: ASSEMBLY: DISPLAYPORT; CDS_LIB: discrete; CDS_PART_NAME: R_0402-0OHM,0.05 OHM,62.5MW,195-2655-000; CDS_PHYS_PART_NAME: R_0402-0OHM,0.05 OHM,62.5MW,195-2655-000-0OHM,195-2655-000; CDS_SEC: 1; CHIPS_PART_NAME: R; DEVICE_TYPENAME: R_0402-0OHM005OHM625MW195-2655-000-0OHM195-2655-000; DRAWING: #NAME?; MAX_WATTAGE: 62.5mW; NV_PN: 195-2655-000; PATH: I35; PHYS_PAGE: 17; PLACEMENT_NOTE: CoLayout with L501; ROT: 0; SEC: 1; SIGNAL_MODEL: nv_res; TOL: 0.05 ohm; VER: 1; XY: (-6500,4450)
R78 = R#1: ASSEMBLY: DISPLAYPORT; CDS_LIB: discrete; CDS_PART_NAME: R_0402-0OHM,0.05 OHM,62.5MW,195-2655-000; CDS_PHYS_PART_NAME: R_0402-0OHM,0.05 OHM,62.5MW,195-2655-000-0OHM,195-2655-000; CDS_SEC: 1; CHIPS_PART_NAME: R; DEVICE_TYPENAME: R_0402-0OHM005OHM625MW195-2655-000-0OHM195-2655-000; DRAWING: #NAME?; MAX_WATTAGE: 62.5mW; NV_PN: 195-2655-000; PATH: I37; PHYS_PAGE: 17; PLACEMENT_NOTE: CoLayout with L501; ROT: 0; SEC: 1; SIGNAL_MODEL: nv_res; TOL: 0.05 ohm; VER: 1; XY: (-6500,4100)
R79 = R#1: ASSEMBLY: DISPLAYPORT; CDS_LIB: discrete; CDS_PART_NAME: R_0402-0OHM,0.05 OHM,62.5MW,195-2655-000; CDS_PHYS_PART_NAME: R_0402-0OHM,0.05 OHM,62.5MW,195-2655-000-0OHM,195-2655-000; CDS_SEC: 1; CHIPS_PART_NAME: R; DEVICE_TYPENAME: R_0402-0OHM005OHM625MW195-2655-000-0OHM195-2655-000; DRAWING: #NAME?; MAX_WATTAGE: 62.5mW; NV_PN: 195-2655-000; PATH: I38; PHYS_PAGE: 17; PLACEMENT_NOTE: CoLayout with L503; ROT: 0; SEC: 1; SIGNAL_MODEL: nv_res; TOL: 0.05 ohm; VER: 1; XY: (-6500,3800)
R80 = R#1: ASSEMBLY: DISPLAYPORT; CDS_LIB: discrete; CDS_PART_NAME: R_0402-0OHM,0.05 OHM,62.5MW,195-2655-000; CDS_PHYS_PART_NAME: R_0402-0OHM,0.05 OHM,62.5MW,195-2655-000-0OHM,195-2655-000; CDS_SEC: 1; CHIPS_PART_NAME: R; DEVICE_TYPENAME: R_0402-0OHM005OHM625MW195-2655-000-0OHM195-2655-000; DRAWING: #NAME?; MAX_WATTAGE: 62.5mW; NV_PN: 195-2655-000; PATH: I45; PHYS_PAGE: 17; PLACEMENT_NOTE: CoLayout with L503; ROT: 0; SEC: 1; SIGNAL_MODEL: nv_res; TOL: 0.05 ohm; VER: 1; XY: (-6500,3450)
R81 = R#1: ASSEMBLY: DISPLAYPORT; CDS_LIB: discrete; CDS_PART_NAME: R_0402-0OHM,0.05 OHM,62.5MW,195-2655-000; CDS_PHYS_PART_NAME: R_0402-0OHM,0.05 OHM,62.5MW,195-2655-000-0OHM,195-2655-000; CDS_SEC: 1; CHIPS_PART_NAME: R; DEVICE_TYPENAME: R_0402-0OHM005OHM625MW195-2655-000-0OHM195-2655-000; DRAWING: #NAME?; MAX_WATTAGE: 62.5mW; NV_PN: 195-2655-000; PATH: I46; PHYS_PAGE: 17; PLACEMENT_NOTE: CoLayout with L504; ROT: 0; SEC: 1; SIGNAL_MODEL: nv_res; TOL: 0.05 ohm; VER: 1; XY: (-6500,3150)
R82 = R#1: ASSEMBLY: DISPLAYPORT; CDS_LIB: discrete; CDS_PART_NAME: R_0402-0OHM,0.05 OHM,62.5MW,195-2655-000; CDS_PHYS_PART_NAME: R_0402-0OHM,0.05 OHM,62.5MW,195-2655-000-0OHM,195-2655-000; CDS_SEC: 1; CHIPS_PART_NAME: R; DEVICE_TYPENAME: R_0402-0OHM005OHM625MW195-2655-000-0OHM195-2655-000; DRAWING: #NAME?; MAX_WATTAGE: 62.5mW; NV_PN: 195-2655-000; PATH: I48; PHYS_PAGE: 17; PLACEMENT_NOTE: CoLayout with L504; ROT: 0; SEC: 1; SIGNAL_MODEL: nv_res; TOL: 0.05 ohm; VER: 1; XY: (-6500,2800)
R83 = R#1: ASSEMBLY: DISPLAYPORT; CDS_LIB: discrete; CDS_PART_NAME: R_0402-0OHM,0.05 OHM,62.5MW,195-2655-000; CDS_PHYS_PART_NAME: R_0402-0OHM,0.05 OHM,62.5MW,195-2655-000-0OHM,195-2655-000; CDS_SEC: 1; CHIPS_PART_NAME: R; DEVICE_TYPENAME: R_0402-0OHM005OHM625MW195-2655-000-0OHM195-2655-000; DRAWING: #NAME?; MAX_WATTAGE: 62.5mW; NV_PN: 195-2655-000; PATH: I49; PHYS_PAGE: 17; PLACEMENT_NOTE: CoLayout with L506; ROT: 0; SEC: 1; SIGNAL_MODEL: nv_res; TOL: 0.05 ohm; VER: 1; XY: (-6500,2500)
R84 = R#1: ASSEMBLY: DISPLAYPORT; CDS_LIB: discrete; CDS_PART_NAME: R_0402-0OHM,0.05 OHM,62.5MW,195-2655-000; CDS_PHYS_PART_NAME: R_0402-0OHM,0.05 OHM,62.5MW,195-2655-000-0OHM,195-2655-000; CDS_SEC: 1; CHIPS_PART_NAME: R; DEVICE_TYPENAME: R_0402-0OHM005OHM625MW195-2655-000-0OHM195-2655-000; DRAWING: #NAME?; MAX_WATTAGE: 62.5mW; NV_PN: 195-2655-000; PATH: I51; PHYS_PAGE: 17; PLACEMENT_NOTE: CoLayout with L506; ROT: 0; SEC: 1; SIGNAL_MODEL: nv_res; TOL: 0.05 ohm; VER: 1; XY: (-6500,2150)
R85 = R#1: ASSEMBLY: DISPLAYPORT; CDS_LIB: discrete; CDS_PART_NAME: R_0402-5.1K,5 %,62.5MW,195-0605-000; CDS_PHYS_PART_NAME: R_0402-5.1K,5 %,62.5MW,195-0605-000-195-0605-000,5.1K; CDS_SEC: 1; CHIPS_PART_NAME: R; DEVICE_TYPENAME: R_0402-51K5625MW195-0605-000-195-0605-00051K; DRAWING: #NAME?; MAX_WATTAGE: 62.5mW; NV_PN: 195-0605-000; PATH: I28; PHYS_PAGE: 17; ROT: 0; SEC: 1; SIGNAL_MODEL: nv_res; TOL: 5%; VER: 1; XY: (-5800,6750)
R86 = R: ASSEMBLY: DISPLAYPORT; CDS_LIB: discrete; CDS_PART_NAME: R_0402-5.1K,5 %,62.5MW,195-0605-000; CDS_PHYS_PART_NAME: R_0402-5.1K,5 %,62.5MW,195-0605-000-195-0605-000,5.1K; CDS_SEC: 1; DEVICE_TYPENAME: R_0402-51K5625MW195-0605-000-195-0605-00051K; DRAWING: #NAME?; MAX_WATTAGE: 62.5mW; NV_PN: 195-0605-000; PATH: I26; PHYS_PAGE: 17; ROT: 2; SEC: 1; SIGNAL_MODEL: nv_res; TOL: 5%; VER: 2; XY: (-5400,7050)
R87 = R: ASSEMBLY: DISPLAYPORT; CDS_LIB: discrete; CDS_PART_NAME: R_0402-100K,1 %,62.5MW,195-0005-000; CDS_PHYS_PART_NAME: R_0402-100K,1 %,62.5MW,195-0005-000-100K,195-0005-000; CDS_SEC: 1; DEVICE_TYPENAME: R_0402-100K1625MW195-0005-000-100K195-0005-000; DRAWING: #NAME?; MAX_WATTAGE: 62.5mW; NV_PN: 195-0005-000; PATH: I23; PHYS_PAGE: 17; ROT: 2; SEC: 1; SIGNAL_MODEL: nv_res; TOL: 1%; VER: 2; XY: (-4900,6400)
R88 = R: ASSEMBLY: DISPLAYPORT; CDS_LIB: discrete; CDS_PART_NAME: R_0402-100K,1 %,62.5MW,195-0005-000; CDS_PHYS_PART_NAME: R_0402-100K,1 %,62.5MW,195-0005-000-100K,195-0005-000; CDS_SEC: 1; DEVICE_TYPENAME: R_0402-100K1625MW195-0005-000-100K195-0005-000; DRAWING: #NAME?; MAX_WATTAGE: 62.5mW; NV_PN: 195-0005-000; PATH: I16; PHYS_PAGE: 17; ROT: 3; SEC: 1; SIGNAL_MODEL: nv_res; TOL: 1%; VER: 2; XY: (-4600,6550)
R89 = R: ASSEMBLY: DISPLAYPORT; CDS_LIB: discrete; CDS_PART_NAME: R_0402-100K,1 %,62.5MW,195-0005-000; CDS_PHYS_PART_NAME: R_0402-100K,1 %,62.5MW,195-0005-000-100K,195-0005-000; CDS_SEC: 1; DEVICE_TYPENAME: R_0402-100K1625MW195-0005-000-100K195-0005-000; DRAWING: #NAME?; MAX_WATTAGE: 62.5mW; NV_PN: 195-0005-000; PATH: I19; PHYS_PAGE: 17; ROT: 2; SEC: 1; SIGNAL_MODEL: nv_res; TOL: 1%; VER: 2; XY: (-4800,5150)
R90 = R: ASSEMBLY: DISPLAYPORT; CDS_LIB: discrete; CDS_PART_NAME: R_0402-100K,1 %,62.5MW,195-0005-000; CDS_PHYS_PART_NAME: R_0402-100K,1 %,62.5MW,195-0005-000-100K,195-0005-000; CDS_SEC: 1; DEVICE_TYPENAME: R_0402-100K1625MW195-0005-000-100K195-0005-000; DRAWING: #NAME?; MAX_WATTAGE: 62.5mW; NV_PN: 195-0005-000; PATH: I18; PHYS_PAGE: 17; ROT: 2; SEC: 1; SIGNAL_MODEL: nv_res; TOL: 1%; VER: 2; XY: (-4800,5600)
R91 = R#1: ASSEMBLY: DISPLAYPORT; CDS_LIB: discrete; CDS_PART_NAME: R_0402-0OHM,0.05 OHM,62.5MW,195-2655-000; CDS_PHYS_PART_NAME: R_0402-0OHM,0.05 OHM,62.5MW,195-2655-000-0OHM,195-2655-000; CDS_SEC: 1; CHIPS_PART_NAME: R; DEVICE_TYPENAME: R_0402-0OHM005OHM625MW195-2655-000-0OHM195-2655-000; DRAWING: #NAME?; MAX_WATTAGE: 62.5mW; NV_PN: 195-2655-000; PATH: I6; PHYS_PAGE: 17; ROT: 2; SEC: 1; SIGNAL_MODEL: nv_res; TOL: 0.05 ohm; VER: 1; XY: (-2500,5850)
R92 = R: ASSEMBLY: DISPLAYPORT; CDS_LIB: discrete; CDS_PART_NAME: R_0402-24.9K,1 %,62.5MW,195-0195-000; CDS_PHYS_PART_NAME: R_0402-24.9K,1 %,62.5MW,195-0195-000-195-0195-000,24.9K; CDS_SEC: 1; DEVICE_TYPENAME: R_0402-249K1625MW195-0195-000-195-0195-000249K; DRAWING: #NAME?; MAX_WATTAGE: 62.5mW; NV_PN: 195-0195-000; PATH: I1; PHYS_PAGE: 17; ROT: 0; SEC: 1; SIGNAL_MODEL: nv_res; TOL: 1%; VER: 2; XY: (-950,5550)
R192 = R#1: ASSEMBLY: DISPLAYPORT; CDS_LIB: discrete; CDS_PART_NAME: R_0402-100K,1 %,62.5MW,195-0005-000; CDS_PHYS_PART_NAME: R_0402-100K,1 %,62.5MW,195-0005-000-100K,195-0005-000; CDS_SEC: 1; CHIPS_PART_NAME: R; DEVICE_TYPENAME: R_0402-100K1625MW195-0005-000-100K195-0005-000; DRAWING: #NAME?; MAX_WATTAGE: 62.5mW; NV_PN: 195-0005-000; PATH: I88; PHYS_PAGE: 17; ROT: 2; SEC: 1; SIGNAL_MODEL: nv_res; TOL: 1%; VER: 1; XY: (-8900,5850)
R193 = R#1: ASSEMBLY: DISPLAYPORT; CDS_LIB: discrete; CDS_PART_NAME: R_0402-100K,1 %,62.5MW,195-0005-000; CDS_PHYS_PART_NAME: R_0402-100K,1 %,62.5MW,195-0005-000-100K,195-0005-000; CDS_SEC: 1; CHIPS_PART_NAME: R; DEVICE_TYPENAME: R_0402-100K1625MW195-0005-000-100K195-0005-000; DRAWING: #NAME?; MAX_WATTAGE: 62.5mW; NV_PN: 195-0005-000; PATH: I87; PHYS_PAGE: 17; ROT: 2; SEC: 1; SIGNAL_MODEL: nv_res; TOL: 1%; VER: 1; XY: (-8900,5000)
R194 = R: ASSEMBLY: DISPLAYPORT; CDS_LIB: discrete; CDS_PART_NAME: R_0402-1M,5 %,62.5MW,195-0488-000; CDS_PHYS_PART_NAME: R_0402-1M,5 %,62.5MW,195-0488-000-195-0488-000,1M; CDS_SEC: 1; DEVICE_TYPENAME: R_0402-1M5625MW195-0488-000-195-0488-0001M; DRAWING: #NAME?; MAX_WATTAGE: 62.5mW; NV_PN: 195-0488-000; PATH: I84; PHYS_PAGE: 17; ROT: 0; SEC: 1; SIGNAL_MODEL: DEFAULT_RESISTOR_0.001OHM_2_1; TOL: 5%; VER: 2; XY: (-1700,3750)
U10 = U_PWR_SW_UL: ASSEMBLY: DISPLAYPORT; CDS_LIB: power_supply; CDS_PART_NAME: U_PWR_SW_UL_SOT23_5_EFU-APL3552ABI-TRG,2.7V..5.5V,2.7V..5.5V,2A,SWITCH,315-1062-000; CDS_PHYS_PART_NAME: U_PWR_SW_UL_SOT23_5_EFU-APL3552ABI-TRG,2.7V..5.5V,2.7V..5.5V,2A,SWITCH,315-1062-000-315-1062-000; CDS_SEC: 1; DEVICE_TYPENAME: U_PWR_SW_UL_SOT23_5_EFU-APL3552ABI-TRG27V55V27V55V2ASWITCH315-1062-000-315-1062-000; DRAWING: #NAME?; FUNCTION: Power Switch; MAX_CURRENT: 2A; MAX_VOLTAGE: 2.7V..5.5V; NV_NAME: APL3552ABI-TRG; NV_PN: 315-1062-000; OUTPUT_VOLTAGE: 2.7V..5.5V; PACK_TYPE: SOT23_5_EFU; PATH: I4; PHYS_PAGE: 17; ROT: 0; SEC: 1; TYPE: Switch; VER: 1; XY: (-1650,5850)
U27 = U_LEVSHFT_3STATE: ASSEMBLY: DISPLAYPORT; CDS_LIB: logic; CDS_PART_NAME: U_LEVSHFT_3STATE_SC70_5-SN74LV1T125,LEVEL SHIFTER,115-2747-000; CDS_PHYS_PART_NAME: U_LEVSHFT_3STATE_SC70_5-SN74LV1T125,LEVEL SHIFTER,115-2747-000-115-2747-000; CDS_SEC: 1; DEVICE_TYPENAME: U_LEVSHFT_3STATE_SC70_5-SN74LV1T125LEVELSHIFTER115-2747-000-115-2747-000; DRAWING: #NAME?; FUNCTION: Level Shifter; NV_NAME: SN74LV1T125; NV_PN: 115-2747-000; PATH: I108; PHYS_PAGE: 17; ROT: 0; SEC: 1; VER: 10; XY: (-10500,6200)

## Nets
GND: C104.2 C105.2 C174.2 D21.3(GND1) D22.3(GND1) D23.3(GND1) J8.21(GND_1) J8.24(GND_2) J8.27(GND_3) J8.30(GND_4) J8.35(GND_7) J8.38(PWR_RET) Q15.2(E) Q16.2(E) R87.2 R89.2 R92.2 R192.2 R193.2 R194.2 U10.2(GND) U27.1(OE*) U27.3(GND) ; also on sheet 1 2 3 4 5 6 7 9 10 11 12 13 14 15 16 17 18 19 21
VDD_1V8: R76.1 R86.1 ; also on sheet 2 3 4 5 9 15 19 21
VDD_3V3_DP: C105.1 C174.1 J8.39(PWR) R90.1 U10.1(OUT)
VDD_3V3_SYS: U10.5(IN) ; also on sheet 2 3 4 5 6 7 9 12 15 16 19 20 21
VDD_5V_SYS: U27.5(VCC) ; also on sheet 2 3 9 10 11 12 14 15 16 17 21
BUCK_3V3_PG: R91.2 ; also on sheet 12 14 15 16
DP0_AUX_N: Q30.2(S) R192.1 ; also on sheet 19
DP0_AUX_P: Q31.2(S) R193.1 ; also on sheet 19
DP0_AUX_Q_N: Q32.3(D) Q34.3(D)
DP0_AUX_Q_P: Q33.3(D) Q35.3(D)
DP0_AUX_R_N: C102.1 Q30.3(D) Q32.2(S)
DP0_AUX_R_P: C103.1 Q31.3(D) Q33.2(S)
DP0_HPD: Q15.3(C) R76.2 ; also on sheet 19
DP0_HPD_B: Q15.1(B) R85.1
DP0_HPD_C: Q16.3(C) R85.2 R86.2
DP0_TXD0_N: C97.1 ; also on sheet 19
DP0_TXD0_P: C101.1 ; also on sheet 19
DP0_TXD1_N: C96.1 ; also on sheet 19
DP0_TXD1_P: C100.1 ; also on sheet 19
DP0_TXD2_N: C95.1 ; also on sheet 19
DP0_TXD2_P: C99.1 ; also on sheet 19
DP0_TXD3_N: C94.1 ; also on sheet 19
DP0_TXD3_P: C98.1 ; also on sheet 19
DP_CON_AUXN: C102.2 D21.4(3A) D21.7(3B) J8.36(AUXN) Q34.2(S) R90.2
DP_CON_AUXP: C103.2 D21.5(4A) D21.6(4B) J8.34(AUXP) Q35.2(S) R89.1
DP_CON_LANE0_N: D22.4(3A) D22.7(3B) J8.22(LANE_0N) L18.1 R83.2
DP_CON_LANE0_P: D22.5(4A) D22.6(4B) J8.20(LANE_0P) L18.2 R84.2
DP_CON_LANE0_R_N: C97.2 L18.4 R83.1
DP_CON_LANE0_R_P: C101.2 L18.3 R84.1
DP_CON_LANE1_N: D23.2(2A) D23.9(2B) J8.25(LANE_1N) L17.2 R81.2
DP_CON_LANE1_P: D23.1(1A) D23.10(1B) J8.23(LANE_1P) L17.1 R82.2
DP_CON_LANE1_R_N: C96.2 L17.3 R81.1
DP_CON_LANE1_R_P: C100.2 L17.4 R82.1
DP_CON_LANE2_N: D22.1(1A) D22.10(1B) J8.28(LANE_2N) L16.1 R79.2
DP_CON_LANE2_P: D22.2(2A) D22.9(2B) J8.26(LANE_2P) L16.2 R80.2
DP_CON_LANE2_R_N: C95.2 L16.4 R79.1
DP_CON_LANE2_R_P: C99.2 L16.3 R80.1
DP_CON_LANE3_N: D23.5(4A) D23.6(4B) J8.31(LANE_3N) L15.2 R77.2
DP_CON_LANE3_P: D23.4(3A) D23.7(3B) J8.29(LANE_3P) L15.1 R78.2
DP_CON_LANE3_R_N: C94.2 L15.3 R77.1
DP_CON_LANE3_R_P: C98.2 L15.4 R78.1
DP_HPD_CON: C104.1 D21.1(1A) D21.10(1B) J8.37(HPD) R88.2
DP_HPD_CON_R: Q16.1(B) R87.1 R88.1
DP_ILIM: R92.1 U10.3(OC*)
DP_MODE: J8.32(MODE) R194.1 U27.2(IN)
DP_MODE_LS: Q32.1(G) Q33.1(G) Q34.1(G) Q35.1(G) U27.4(OUT)
DP_SW_EN: R91.1 U10.4(EN)
POWER_EN: Q30.1(G) Q31.1(G) ; also on sheet 14 21
SNN_DP_CEC: J8.33(CEC_DP)
SNN_ESD_D27: D21.2(2A) D21.9(2B)

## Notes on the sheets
sheet 8
- A
- B
- C
- D
- E
- F
- G
- H
- DisplayPort Connector
- 1
- 1
- 2
- 2
- PCB CO-LAYOUT
- PCB CO-LAYOUT
- 3
- 3
- PCB CO-LAYOUT
- PCB CO-LAYOUT
- 4
- 4
- 5
- 5
- NVIDIA CORPORATION
- 2701 SAN TOMAS EXPRESSWAY
- ASSEMBLY
- <ASSEMBLY_DESCRIPTION>
- SANTA CLARA, CA 95050, USA
- PAGE DETAIL
- DISPLAY PORT
- NV_PN
- 600-13509-BASE-100
- ALL NVIDIA DESIGN SPECIFICATIONS, REFERENCE SPECIFICATIONS, REFERENCE BOARDS, FILES, DRAWINGS, DIAGNOSTICS, LISTS AND OTHER DOCUMENTS OR INFORMATION (TOGETHER AND SEPARATELY, 'MATERIALS') ARE BEING PROVIDED 'AS IS'. THE MATERIALS MAY
- CONTAIN KNOWN AND UNKNOWN VIOLATIONS OR DEVIATIONS OF INDUSTRY STANDARDS AND SPECIFICATIONS. NVIDIA MAKES NO WARRANTIES, EXPRESSED, IMPLIED, STATUTORY OR OTHERWISE WITH RESPECT TO THE MATERIALS OR OTHERWISE, AND EXPRESSLY DISCLAIMS ALL
- PCB REV
- P3509-A01
- PAGE
- 17 OF 25
- IMPLIED WARRANTIES INCLUDING, WITHOUT LIMITATION, THE WARRANTIES OF DESIGN, OF NONINFRINGEMENT, MERCHANTABILITY OR FITNESS FOR A PARTICULAR PURPOSE, OR ARISING FROM A COURSE OF DEALING, TRADE USAGE, TRADE PRACTICE, OR INDUSTRY STANDARDS.
- BOM REV
- <BOM_REV>
- DATE
- 27-NOV-2019
- A
- B
- C
- D
- E
- F
- G
- H
